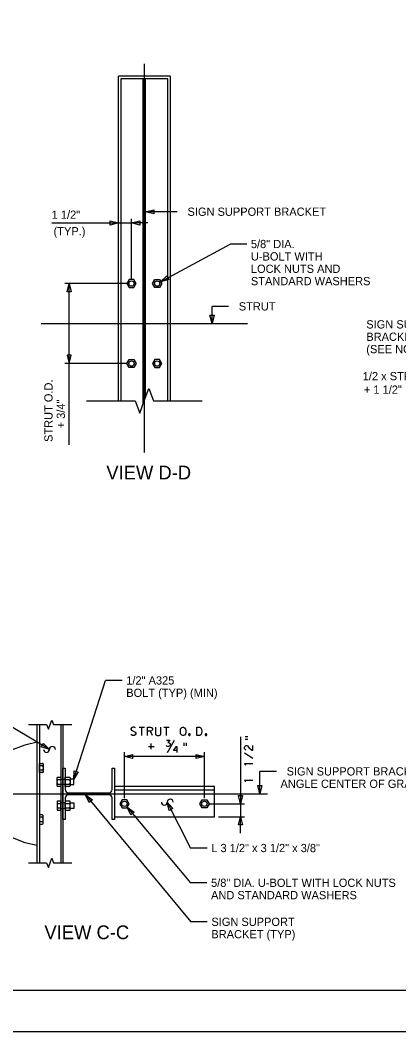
# Model space of a CAD drawing. Extents: x 3829340 to 3831660, y 499389 to 501171.
# Drawn here: x 3830479 to 3830616.6, y 499389.2 to 499757.1 of the extents above; entities that cross this region are included whole.
import ezdxf

# ---------------------------------------------------------------- set-up
doc = ezdxf.new("R2010")
doc.units = 0
for name, color, linetype in [('0-ANCHOR', 7, 'Continuous'), ('2', 7, 'Continuous'), ('CNTR', 7, 'Continuous'), ('Default', 7, 'Continuous'), ('DIM TXT', 7, 'Continuous'), ('PLT-BNDY', 7, 'Continuous'), ('sign', 7, 'Continuous'), ('structure', 7, 'Continuous')]:
    doc.layers.add(name, color=color, linetype=linetype)

msp = doc.modelspace()

# ---------------------------------------------------------------- linework, layer by layer
at = {"layer": '0-ANCHOR'}
for p, q in [((3830485.94, 499483.47), (3830485.94, 499486.79)), ((3830485.94, 499486.79), (3830487.12, 499486.79)), ((3830487.12, 499485.96), (3830485.94, 499485.96)), ((3830487.12, 499484.3), (3830485.94, 499484.3)), ((3830487.31, 499486.6), (3830487.31, 499483.66)), ((3830487.12, 499483.47), (3830485.94, 499483.47)), ((3830492.38, 499478.61), (3830492.38, 499481.56)), ((3830492.57, 499481.74), (3830493.75, 499481.74)), ((3830492.57, 499480.91), (3830493.75, 499480.91)), ((3830493.75, 499481.74), (3830493.75, 499478.42)), ((3830493.75, 499481.06), (3830495.34, 499481.06)), ((3830495.34, 499478.42), (3830495.34, 499481.74)), ((3830495.34, 499481.74), (3830496.91, 499481.74)), ((3830495.34, 499481.06), (3830495.34, 499479.11)), ((3830495.34, 499480.91), (3830496.91, 499480.91)), ((3830497.1, 499481.56), (3830497.1, 499478.61)), ((3830498.45, 499481.06), (3830497.1, 499481.06)), ((3830498.45, 499479.11), (3830498.45, 499481.06)), ((3830492.57, 499479.25), (3830493.75, 499479.25)), ((3830493.75, 499478.42), (3830492.57, 499478.42)), ((3830495.34, 499479.11), (3830493.75, 499479.11)), ((3830495.34, 499479.25), (3830496.91, 499479.25)), ((3830496.91, 499478.42), (3830495.34, 499478.42)), ((3830497.1, 499479.11), (3830498.45, 499479.11)), ((3830492.38, 499472.9), (3830492.38, 499469.95)), ((3830493.75, 499473.09), (3830492.57, 499473.09)), ((3830493.75, 499469.77), (3830493.75, 499473.09)), ((3830496.91, 499473.09), (3830495.34, 499473.09)), ((3830495.34, 499473.09), (3830495.34, 499469.77)), ((3830497.1, 499469.95), (3830497.1, 499472.9)), ((3830516.01, 499473.58), (3830515.15, 499472.1)), ((3830517.72, 499473.58), (3830516.01, 499473.58)), ((3830518.57, 499472.1), (3830517.72, 499473.58)), ((3830544.25, 499472.1), (3830545.11, 499473.58)), ((3830545.11, 499473.58), (3830546.82, 499473.58)), ((3830546.82, 499473.58), (3830547.67, 499472.1)), ((3830492.57, 499472.26), (3830493.75, 499472.26)), ((3830492.57, 499470.6), (3830493.75, 499470.6)), ((3830492.57, 499469.77), (3830493.75, 499469.77)), ((3830495.34, 499472.4), (3830493.75, 499472.4)), ((3830493.75, 499470.45), (3830495.34, 499470.45)), ((3830495.34, 499470.45), (3830495.34, 499472.4)), ((3830495.34, 499472.26), (3830496.91, 499472.26)), ((3830495.34, 499470.6), (3830496.91, 499470.6)), ((3830495.34, 499469.77), (3830496.91, 499469.77)), ((3830497.1, 499472.4), (3830498.45, 499472.4)), ((3830498.45, 499470.45), (3830497.1, 499470.45)), ((3830498.45, 499472.4), (3830498.45, 499470.45)), ((3830515.15, 499472.1), (3830516.01, 499470.62)), ((3830516.01, 499470.62), (3830517.72, 499470.62)), ((3830517.72, 499470.62), (3830518.57, 499472.1)), ((3830545.11, 499470.62), (3830544.25, 499472.1)), ((3830546.82, 499470.62), (3830545.11, 499470.62)), ((3830547.67, 499472.1), (3830546.82, 499470.62)), ((3830487.12, 499468.04), (3830485.94, 499468.04)), ((3830485.94, 499468.04), (3830485.94, 499464.72)), ((3830487.12, 499467.21), (3830485.94, 499467.21)), ((3830487.12, 499465.55), (3830485.94, 499465.55)), ((3830487.31, 499464.91), (3830487.31, 499467.85)), ((3830485.94, 499464.72), (3830487.12, 499464.72))]:
    msp.add_line(p, q, dxfattribs=at)
for centre in [(3830516.86, 499472.1), (3830545.96, 499472.1)]:
    msp.add_circle(centre, 0.977, dxfattribs=at)
for centre, start, end in [((3830487.12, 499486.6), 360, 90), ((3830487.12, 499486.15), 270, 0), ((3830487.12, 499484.11), 360, 90), ((3830487.12, 499483.66), 270, 0), ((3830492.57, 499481.56), 90, 180), ((3830492.57, 499481.1), 180, 270), ((3830496.91, 499481.56), 360, 90), ((3830496.91, 499481.1), 270, 0), ((3830492.57, 499479.07), 90, 180), ((3830492.57, 499478.61), 180, 270), ((3830496.91, 499479.07), 360, 90), ((3830496.91, 499478.61), 270, 0), ((3830492.57, 499472.9), 90, 180), ((3830496.91, 499472.9), 360, 90), ((3830492.57, 499472.44), 180, 270), ((3830492.57, 499470.41), 90, 180), ((3830492.57, 499469.95), 180, 270), ((3830496.91, 499472.44), 270, 0), ((3830496.91, 499470.41), 360, 90), ((3830496.91, 499469.95), 270, 0), ((3830487.12, 499467.85), 360, 90), ((3830487.12, 499467.4), 270, 0), ((3830487.12, 499465.36), 360, 90), ((3830487.12, 499464.91), 270, 0)]:
    msp.add_arc(centre, 0.187, start, end, dxfattribs=at)
for centre, major_axis, start_param, end_param in [((3830487.12, 499485.44), (0, 0.518), 4.712389, 6.283185), ((3830487.12, 499484.82), (0, -0.518), 0, 1.570796), ((3830492.57, 499480.39), (0, 0.518), 0, 1.570796), ((3830496.91, 499480.39), (0, 0.518), 4.712389, 6.283185), ((3830492.57, 499479.77), (0, -0.518), 4.712389, 6.283185), ((3830496.91, 499479.77), (0, -0.518), 0, 1.570796), ((3830492.57, 499471.74), (0, 0.518), 0, 1.570796), ((3830492.57, 499471.11), (0, -0.518), 4.712389, 6.283185), ((3830496.91, 499471.74), (0, 0.518), 4.712389, 6.283185), ((3830496.91, 499471.11), (0, -0.518), 0, 1.570796), ((3830487.12, 499466.69), (0, 0.518), 4.712389, 6.283185), ((3830487.12, 499466.07), (0, -0.518), 0, 1.570796)]:
    msp.add_ellipse(centre, major_axis=major_axis, ratio=0.362172, start_param=start_param, end_param=end_param, dxfattribs=at)
at = {"layer": '2'}
msp.add_line((3831006.96, 499404.19), (3830220.96, 499404.19), dxfattribs=at)
at = {"layer": 'CNTR'}
for p, q in [((3830524.11, 499741.25), (3830524.11, 499599.92)), ((3830486.61, 499646.79), (3830561.61, 499646.79)), ((3830460.93, 499475.75), (3830568.91, 499475.75))]:
    msp.add_line(p, q, dxfattribs=at)
at = {"layer": 'Default'}
for p, q in [((3830496, 499658.34), (3830496.75, 499661.34)), ((3830496.75, 499661.34), (3830497.5, 499658.34)), ((3830497.5, 499658.34), (3830496, 499658.34)), ((3830497.5, 499635.24), (3830496, 499635.24)), ((3830496, 499635.24), (3830496.75, 499632.24)), ((3830496.75, 499632.24), (3830497.5, 499635.24))]:
    msp.add_line(p, q, dxfattribs=at)
at = {"layer": 'DIM TXT'}
for p, q in [((3830536.11, 499687.41), (3830524.56, 499687.41)), ((3830490.43, 499683.38), (3830514.75, 499683.38)), ((3830514.75, 499676.41), (3830514.75, 499684.88)), ((3830514.75, 499683.38), (3830519.44, 499683.38)), ((3830519.44, 499662.84), (3830519.44, 499684.88)), ((3830525.44, 499683.38), (3830519.44, 499683.38)), ((3830530.05, 499662.02), (3830555.36, 499675.72)), ((3830561.36, 499675.72), (3830555.36, 499675.72)), ((3830517.94, 499661.34), (3830495.25, 499661.34)), ((3830496.75, 499632.24), (3830496.75, 499661.34)), ((3830548.74, 499646.79), (3830548.74, 499653.04)), ((3830554.74, 499653.04), (3830548.74, 499653.04)), ((3830517.94, 499632.24), (3830495.25, 499632.24)), ((3830496.75, 499602.64), (3830496.75, 499632.24)), ((3830524.11, 499618.67), (3830525.78, 499623.18)), ((3830525.78, 499623.18), (3830527.44, 499618.67)), ((3830503.1, 499618.67), (3830520.78, 499618.67)), ((3830520.78, 499618.67), (3830522.44, 499614.16)), ((3830522.44, 499614.16), (3830524.11, 499618.67)), ((3830527.44, 499618.67), (3830545.12, 499618.67)), ((3830498.45, 499481.06), (3830510.04, 499516.99)), ((3830516.04, 499516.99), (3830510.04, 499516.99)), ((3830489.61, 499491.89), (3830462.5, 499508.06)), ((3830489.84, 499500.89), (3830490.47, 499502.58)), ((3830490.47, 499502.58), (3830491.09, 499500.89)), ((3830481.96, 499500.89), (3830488.59, 499500.89)), ((3830488.59, 499500.89), (3830489.22, 499499.2)), ((3830489.22, 499499.2), (3830489.84, 499500.89)), ((3830491.09, 499500.89), (3830497.72, 499500.89)), ((3830522.21, 499499.96), (3830524.19, 499499.96)), ((3830523.2, 499496.96), (3830523.2, 499499.96)), ((3830523.2, 499496.96), (3830523.2, 499499.96)), ((3830531.21, 499499.96), (3830533.19, 499499.96)), ((3830532.2, 499496.96), (3830532.2, 499499.96)), ((3830532.2, 499496.96), (3830532.2, 499499.96)), ((3830527.08, 499496.96), (3830526.39, 499498.49)), ((3830532.57, 499490.74), (3830535.12, 499495.25)), ((3830559.05, 499496.42), (3830559.05, 499472.1)), ((3830561.8, 499496.42), (3830560.73, 499496.42)), ((3830561.8, 499495.47), (3830560.73, 499495.47)), ((3830525.67, 499493), (3830527.63, 499493)), ((3830526.64, 499492.01), (3830526.64, 499493.99)), ((3830538.54, 499493.24), (3830538.54, 499494.3)), ((3830539.49, 499493.24), (3830539.49, 499494.3)), ((3830516.86, 499474.18), (3830516.86, 499490.84)), ((3830516.86, 499489.34), (3830519.86, 499490.09)), ((3830545.96, 499489.34), (3830516.86, 499489.34)), ((3830519.86, 499488.59), (3830516.86, 499489.34)), ((3830519.86, 499490.09), (3830519.86, 499488.59)), ((3830542.96, 499490.09), (3830545.96, 499489.34)), ((3830542.96, 499488.59), (3830542.96, 499490.09)), ((3830545.96, 499489.34), (3830542.96, 499488.59)), ((3830545.96, 499474.18), (3830545.96, 499490.84)), ((3830563.55, 499488.6), (3830560.55, 499490.56)), ((3830563.55, 499486.61), (3830560.55, 499486.61)), ((3830560.55, 499486.61), (3830561.02, 499486.14)), ((3830563.55, 499480.61), (3830560.55, 499480.61)), ((3830560.55, 499480.61), (3830561.02, 499480.14)), ((3830566.12, 499475.75), (3830566.12, 499483.9)), ((3830572.12, 499483.9), (3830566.12, 499483.9)), ((3830502.73, 499475.4), (3830540.99, 499429.18)), ((3830559.05, 499472.1), (3830558.3, 499475.1)), ((3830558.3, 499475.1), (3830559.8, 499475.1)), ((3830559.8, 499475.1), (3830559.05, 499472.1)), ((3830517.88, 499470.91), (3830540.87, 499443.38)), ((3830532.47, 499472.71), (3830540.96, 499456.02)), ((3830547.46, 499472.1), (3830560.55, 499472.1)), ((3830559.05, 499472.1), (3830559.05, 499467.41)), ((3830551.08, 499467.41), (3830560.55, 499467.41)), ((3830558.3, 499464.41), (3830559.05, 499467.41)), ((3830559.05, 499461.41), (3830559.05, 499467.41)), ((3830559.05, 499467.41), (3830559.8, 499464.41)), ((3830559.8, 499464.41), (3830558.3, 499464.41)), ((3830546.96, 499456.02), (3830540.96, 499456.02)), ((3830489.84, 499450.62), (3830490.47, 499452.31)), ((3830490.47, 499452.31), (3830491.09, 499450.62)), ((3830481.96, 499450.62), (3830488.59, 499450.62)), ((3830488.59, 499450.62), (3830489.22, 499448.93)), ((3830489.22, 499448.93), (3830489.84, 499450.62)), ((3830491.09, 499450.62), (3830497.72, 499450.62)), ((3830546.87, 499443.38), (3830540.87, 499443.38)), ((3830546.99, 499429.18), (3830540.99, 499429.18))]:
    msp.add_line(p, q, dxfattribs=at)
for points in [[(3830527.56, 499686.66), (3830524.56, 499687.41), (3830527.56, 499688.16)], [(3830511.75, 499684.13), (3830514.75, 499683.38), (3830511.75, 499682.63)], [(3830522.44, 499682.63), (3830519.44, 499683.38), (3830522.44, 499684.13)], [(3830533.04, 499662.79), (3830530.05, 499662.02), (3830532.33, 499664.11)], [(3830549.49, 499649.79), (3830548.74, 499646.79), (3830547.99, 499649.79)], [(3830487.41, 499494.07), (3830489.61, 499491.89), (3830486.64, 499492.79)], [(3830500.09, 499483.68), (3830498.45, 499481.06), (3830498.66, 499484.14)], [(3830566.87, 499478.75), (3830566.12, 499475.75), (3830565.37, 499478.75)], [(3830504.07, 499472.61), (3830502.73, 499475.4), (3830505.22, 499473.56)], [(3830519.23, 499468.12), (3830517.88, 499470.91), (3830520.38, 499469.09)], [(3830533.16, 499469.7), (3830532.47, 499472.71), (3830534.5, 499470.38)]]:
    msp.add_lwpolyline(points, close=True, dxfattribs=at)
for points in [[(3830520.93, 499499.74), (3830520.46, 499499.96), (3830519.92, 499499.96), (3830519.42, 499499.74), (3830519.21, 499499.36), (3830519.21, 499499.22), (3830519.45, 499498.87), (3830520.82, 499498.16), (3830521.05, 499497.83), (3830521.03, 499497.55), (3830520.82, 499497.17), (3830520.41, 499496.96), (3830519.85, 499496.96), (3830519.59, 499497.05), (3830519.21, 499497.31)], [(3830525.21, 499496.96), (3830525.21, 499499.96), (3830526.41, 499499.96), (3830526.77, 499499.84), (3830527.08, 499499.36), (3830527.08, 499499.08), (3830526.79, 499498.61), (3830526.41, 499498.49), (3830525.21, 499498.49)], [(3830528.21, 499499.96), (3830528.21, 499497.57), (3830528.3, 499497.14), (3830528.73, 499496.96), (3830529.53, 499496.96), (3830529.96, 499497.14), (3830530.1, 499497.57), (3830530.1, 499499.96)], [(3830538.06, 499499.96), (3830538.3, 499499.96), (3830538.7, 499499.79), (3830539.07, 499499.29), (3830539.17, 499498.7), (3830539.17, 499498.16), (3830539.07, 499497.57), (3830538.67, 499497.07), (3830538.3, 499496.96), (3830538.06, 499496.96), (3830537.7, 499497.07), (3830537.3, 499497.57), (3830537.21, 499498.16), (3830537.21, 499498.7), (3830537.3, 499499.32), (3830537.7, 499499.81), (3830538.06, 499499.96)], [(3830543.21, 499499.96), (3830544.29, 499499.96), (3830544.7, 499499.74), (3830544.96, 499499.22), (3830545.07, 499498.54), (3830544.93, 499497.69), (3830544.67, 499497.17), (3830544.29, 499496.96), (3830543.21, 499496.96), (3830543.21, 499499.96)], [(3830532.19, 499495.25), (3830533.37, 499495.25), (3830533.3, 499494.99), (3830533.18, 499494.8), (3830533.02, 499494.61), (3830532.66, 499494.44), (3830532.92, 499494.44), (3830533.2, 499494.33), (3830533.37, 499494.14), (3830533.46, 499493.85), (3830533.46, 499493.55), (3830533.37, 499493.26), (3830533.18, 499493.07), (3830532.92, 499493), (3830532.61, 499493), (3830532.35, 499493.07), (3830532.19, 499493.26)], [(3830540.82, 499497.26), (3830540.82, 499497.29), (3830540.82, 499497.33), (3830540.81, 499497.36), (3830540.8, 499497.39), (3830540.78, 499497.42), (3830540.76, 499497.44), (3830540.74, 499497.47), (3830540.72, 499497.49), (3830540.7, 499497.51), (3830540.67, 499497.53), (3830540.64, 499497.54), (3830540.61, 499497.55), (3830540.58, 499497.56), (3830540.55, 499497.57), (3830540.52, 499497.57), (3830540.48, 499497.57), (3830540.45, 499497.56), (3830540.42, 499497.55), (3830540.39, 499497.54), (3830540.36, 499497.53), (3830540.33, 499497.51), (3830540.31, 499497.49), (3830540.29, 499497.47), (3830540.27, 499497.44), (3830540.25, 499497.42), (3830540.23, 499497.39), (3830540.22, 499497.36), (3830540.22, 499497.33), (3830540.21, 499497.29), (3830540.21, 499497.26), (3830540.21, 499497.23), (3830540.22, 499497.2), (3830540.22, 499497.17), (3830540.23, 499497.14), (3830540.25, 499497.11), (3830540.27, 499497.08), (3830540.29, 499497.06), (3830540.31, 499497.03), (3830540.33, 499497.01), (3830540.36, 499497), (3830540.39, 499496.98), (3830540.42, 499496.97), (3830540.45, 499496.96), (3830540.48, 499496.96), (3830540.52, 499496.96), (3830540.55, 499496.96), (3830540.58, 499496.96), (3830540.61, 499496.97), (3830540.64, 499496.98), (3830540.67, 499497), (3830540.7, 499497.01), (3830540.72, 499497.03), (3830540.74, 499497.06), (3830540.76, 499497.08), (3830540.78, 499497.11), (3830540.8, 499497.14), (3830540.81, 499497.17), (3830540.82, 499497.2), (3830540.82, 499497.23), (3830540.82, 499497.26)], [(3830546.82, 499497.26), (3830546.82, 499497.29), (3830546.82, 499497.33), (3830546.81, 499497.36), (3830546.8, 499497.39), (3830546.78, 499497.42), (3830546.76, 499497.44), (3830546.74, 499497.47), (3830546.72, 499497.49), (3830546.7, 499497.51), (3830546.67, 499497.53), (3830546.64, 499497.54), (3830546.61, 499497.55), (3830546.58, 499497.56), (3830546.55, 499497.57), (3830546.52, 499497.57), (3830546.48, 499497.57), (3830546.45, 499497.56), (3830546.42, 499497.55), (3830546.39, 499497.54), (3830546.36, 499497.53), (3830546.33, 499497.51), (3830546.31, 499497.49), (3830546.29, 499497.47), (3830546.27, 499497.44), (3830546.25, 499497.42), (3830546.23, 499497.39), (3830546.22, 499497.36), (3830546.21, 499497.33), (3830546.21, 499497.29), (3830546.21, 499497.26), (3830546.21, 499497.23), (3830546.21, 499497.2), (3830546.22, 499497.17), (3830546.23, 499497.14), (3830546.25, 499497.11), (3830546.27, 499497.08), (3830546.29, 499497.06), (3830546.31, 499497.03), (3830546.33, 499497.01), (3830546.36, 499497), (3830546.39, 499496.98), (3830546.42, 499496.97), (3830546.45, 499496.96), (3830546.48, 499496.96), (3830546.52, 499496.96), (3830546.55, 499496.96), (3830546.58, 499496.96), (3830546.61, 499496.97), (3830546.64, 499496.98), (3830546.67, 499497), (3830546.7, 499497.01), (3830546.72, 499497.03), (3830546.74, 499497.06), (3830546.76, 499497.08), (3830546.78, 499497.11), (3830546.8, 499497.14), (3830546.81, 499497.17), (3830546.82, 499497.2), (3830546.82, 499497.23), (3830546.82, 499497.26)], [(3830536.13, 499491.52), (3830534.86, 499491.52), (3830534.86, 499491.61), (3830535.85, 499492.98), (3830535.97, 499492.98), (3830535.97, 499490.74)], [(3830561.16, 499491.6), (3830560.88, 499491.69), (3830560.64, 499491.95), (3830560.55, 499492.31), (3830560.55, 499492.57), (3830560.64, 499492.92), (3830560.9, 499493.18), (3830561.16, 499493.3), (3830561.42, 499493.3), (3830561.63, 499493.2), (3830562.08, 499492.61), (3830563.03, 499491.69), (3830563.26, 499491.6), (3830563.55, 499491.6), (3830563.55, 499493.3)]]:
    msp.add_lwpolyline(points, dxfattribs=at)
for centre, start, end in [((3830488.53, 499491.89), 180, 0), ((3830490.68, 499491.89), 0, 180), ((3830533.54, 499472.71), 0, 180), ((3830531.39, 499472.71), 180, 0)]:
    msp.add_arc(centre, 1.08, start, end, dxfattribs=at)
at = {"layer": 'PLT-BNDY'}
msp.add_lwpolyline([(3830180.96, 499983.19), (3831021.96, 499983.19), (3831021.96, 499389.19), (3830180.96, 499389.19)], close=True, dxfattribs=at)
at = {"layer": 'sign'}
for p, q in [((3830518.61, 499662.78), (3830517.78, 499661.34)), ((3830517.78, 499661.34), (3830518.61, 499659.9)), ((3830520.27, 499662.78), (3830518.61, 499662.78)), ((3830521.1, 499661.34), (3830520.27, 499662.78)), ((3830520.27, 499659.9), (3830521.1, 499661.34)), ((3830527.12, 499661.34), (3830527.95, 499662.78)), ((3830527.95, 499659.9), (3830527.12, 499661.34)), ((3830527.95, 499662.78), (3830529.61, 499662.78)), ((3830529.61, 499662.78), (3830530.44, 499661.34)), ((3830530.44, 499661.34), (3830529.61, 499659.9)), ((3830518.61, 499659.9), (3830520.27, 499659.9)), ((3830529.61, 499659.9), (3830527.95, 499659.9)), ((3830517.78, 499632.24), (3830518.61, 499633.68)), ((3830518.61, 499630.8), (3830517.78, 499632.24)), ((3830518.61, 499633.68), (3830520.27, 499633.68)), ((3830520.27, 499633.68), (3830521.1, 499632.24)), ((3830521.1, 499632.24), (3830520.27, 499630.8)), ((3830527.95, 499633.68), (3830527.12, 499632.24)), ((3830527.12, 499632.24), (3830527.95, 499630.8)), ((3830529.61, 499633.68), (3830527.95, 499633.68)), ((3830530.44, 499632.24), (3830529.61, 499633.68)), ((3830529.61, 499630.8), (3830530.44, 499632.24)), ((3830520.27, 499630.8), (3830518.61, 499630.8)), ((3830527.95, 499630.8), (3830529.61, 499630.8)), ((3830485.16, 499450.62), (3830485.16, 499500.89)), ((3830485.94, 499500.89), (3830485.94, 499450.62)), ((3830493.75, 499500.89), (3830493.75, 499450.62)), ((3830494.53, 499500.89), (3830494.53, 499450.62))]:
    msp.add_line(p, q, dxfattribs=at)
for points in [[(3830485.16, 499494.5), (3830480.65, 499493.43), (3830475.45, 499491.46), (3830469.58, 499483.17), (3830468.95, 499475.75)], [(3830468.95, 499475.75), (3830469.58, 499468.34), (3830475.45, 499460.05), (3830480.65, 499458.08), (3830485.16, 499457.01)]]:
    msp.add_lwpolyline(points, dxfattribs=at)
for centre in [(3830519.44, 499661.34), (3830528.78, 499661.34), (3830519.44, 499632.24), (3830528.78, 499632.24)]:
    msp.add_circle(centre, 0.977, dxfattribs=at)
at = {"layer": 'structure'}
for p, q in [((3830533.47, 499736.77), (3830514.75, 499736.77)), ((3830514.75, 499660.27), (3830514.75, 499736.77)), ((3830532.66, 499735.85), (3830515.56, 499735.85)), ((3830515.56, 499735.85), (3830515.56, 499618.67)), ((3830523.66, 499617.56), (3830523.66, 499735.85)), ((3830524.56, 499619.94), (3830524.56, 499735.85)), ((3830532.66, 499618.67), (3830532.66, 499735.85)), ((3830533.47, 499736.77), (3830533.47, 499618.67)), ((3830514.75, 499618.67), (3830514.75, 499660.27)), ((3830549.58, 499478.35), (3830513.25, 499478.35)), ((3830513.25, 499478.35), (3830513.25, 499467.41)), ((3830549.58, 499478.35), (3830513.25, 499478.35)), ((3830513.25, 499478.35), (3830513.25, 499477.18)), ((3830513.25, 499477.18), (3830549.58, 499477.18)), ((3830549.58, 499467.41), (3830549.58, 499478.35)), ((3830549.58, 499477.18), (3830549.58, 499478.35)), ((3830513.25, 499467.41), (3830549.58, 499467.41))]:
    msp.add_line(p, q, dxfattribs=at)
for points in [[(3830495.34, 499474.25), (3830495.34, 499466.4), (3830494.53, 499466.4), (3830494.53, 499485.11), (3830495.34, 499485.11), (3830495.34, 499477.25)], [(3830513.25, 499485.11), (3830513.25, 499466.4), (3830512.44, 499466.4), (3830512.44, 499474.25)], [(3830512.44, 499477.25), (3830512.44, 499485.11), (3830513.25, 499485.11)], [(3830496.48, 499476.11), (3830511.3, 499476.11)], [(3830511.3, 499475.4), (3830496.48, 499475.4)]]:
    msp.add_lwpolyline(points, dxfattribs=at)
for centre, start, end in [((3830496.48, 499477.25), 180, 270), ((3830511.3, 499477.25), 270, 360), ((3830496.48, 499474.25), 90, 180), ((3830511.3, 499474.25), 0, 90)]:
    msp.add_arc(centre, 1.14, start, end, dxfattribs=at)

# ---------------------------------------------------------------- texts
at = {"layer": 'Default'}
for s, p in [('VIEW D-D', (3830510.29, 499590.1)), ('VIEW C-C', (3830487.78, 499422.86))]:
    msp.add_text(s, height=5, dxfattribs=at).set_placement(p)
at = {"layer": 'DIM TXT'}
for s, height, p in [('1 1/2"', 3, (3830490.43, 499684.88)), ('  SIGN SUPPORT BRACKET', 2.9999, (3830537.59, 499685.97)), ('(TYP.)', 3, (3830491.11, 499678.88)), ('5/8" DIA.', 3, (3830562.86, 499674.22)), ('U-BOLT WITH ', 2.9999, (3830562.86, 499669.72)), ('LOCK NUTS AND', 2.9999, (3830562.86, 499665.22)), ('STANDARD WASHERS', 2.9999, (3830562.86, 499660.72)), ('  STRUT', 3, (3830556.22, 499651.54)), ('SIGN SUPPORT', 2.9999, (3830604.82, 499644.99)), ('BRACKET (TYP.)', 2.9999, (3830604.82, 499640.49)), ('(SEE NOTE 1)', 2.9999, (3830604.82, 499635.99)), ('1/2 x STRUT O.D.', 2.9999, (3830603.52, 499626.16)), ('+ 1 1/2"', 3, (3830603.95, 499621.26)), ('1/2" A325', 3, (3830517.54, 499515.49)), ('BOLT (TYP) (MIN)', 2.9999, (3830517.54, 499510.99)), ('  SIGN SUPPORT BRACKET &', 2.9999, (3830573.62, 499482.4)), ('ANGLE CENTER OF GRAVITY', 2.9999, (3830573.62, 499477.9)), ('L 3 1/2" x 3 1/2" x 3/8"', 2.9999, (3830548.46, 499454.52)), ('5/8" DIA. U-BOLT WITH LOCK NUTS', 2.9999, (3830548.37, 499441.88)), ('AND STANDARD WASHERS', 2.9999, (3830548.37, 499437.38)), ('SIGN SUPPORT', 2.9999, (3830548.49, 499427.68)), ('BRACKET (TYP)', 2.9999, (3830548.49, 499423.18))]:
    msp.add_text(s, height=height, dxfattribs=at).set_placement(p)
for s, p in [('STRUT O.D.', (3830490.75, 499603.71)), ('+ 3/4"', (3830495.25, 499608.67))]:
    msp.add_text(s, height=3, rotation=90, dxfattribs=at).set_placement(p)

doc.saveas('drawing.dxf')
